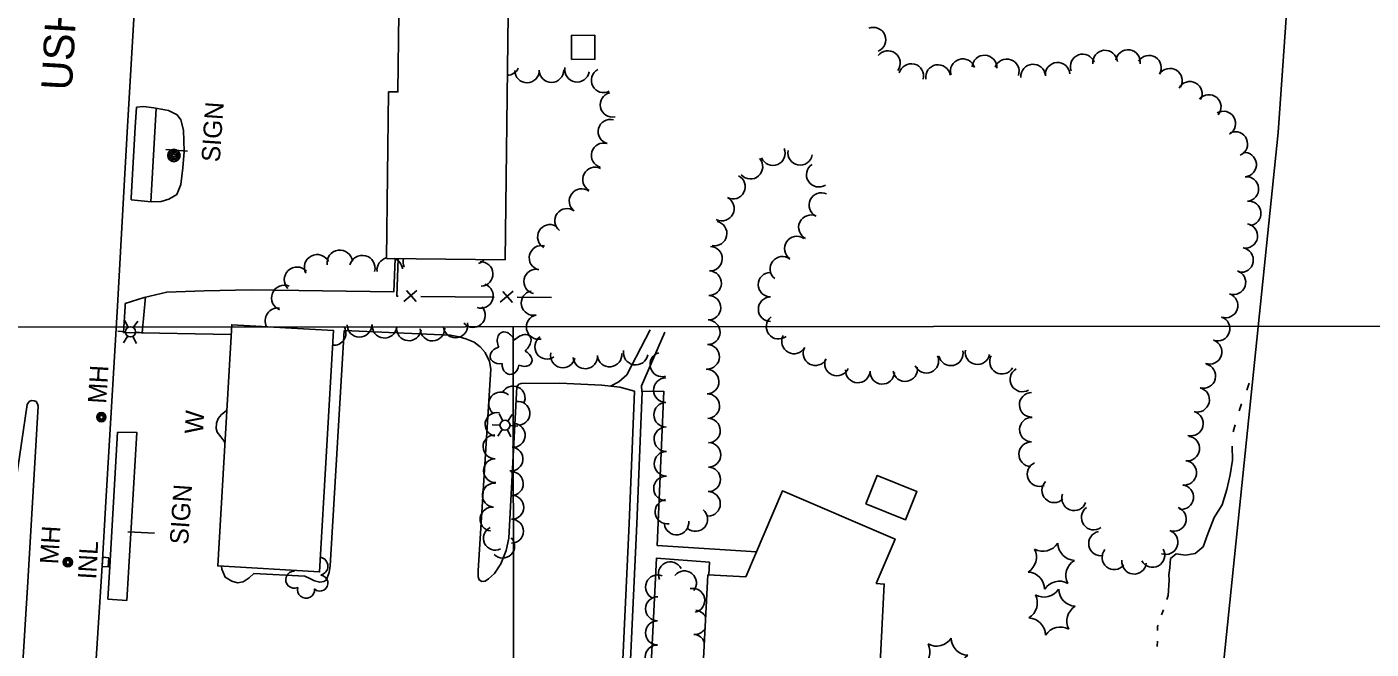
# Model space of a CAD drawing. Extents: x 189384 to 193282, y 256970 to 260388.
# Drawn here: x 190987.6 to 191426.3, y 259406.6 to 259609.6 of the extents above; entities that cross this region are included whole.
import ezdxf

# ---------------------------------------------------------------- set-up
doc = ezdxf.new("R2010")
doc.units = 0
for name, color, linetype in [('E_DRN_Grate', 7, 'Continuous'), ('E_DWY', 7, 'Continuous'), ('E_LAND_Vegetation', 7, 'Continuous'), ('E_MAP_GridLines', 7, 'Continuous'), ('E_MAP_Limits', 7, 'Continuous'), ('E_MISCPROP', 7, 'Continuous'), ('E_MISCPROP_HvyLine', 7, 'Continuous'), ('E_MISCPROP_Railing', 7, 'Continuous'), ('E_PATH_Sidewalk', 7, 'Continuous'), ('E_RDWY', 7, 'Continuous'), ('E_RDWY_Name', 7, 'Continuous'), ('E_WTR', 7, 'Continuous')]:
    doc.layers.add(name, color=color, linetype=linetype)

# ---------------------------------------------------------------- blocks, each defined once
blk = doc.blocks.new('WAL')
at = {"layer": 'E_MISCPROP_Railing'}
blk.add_text('W', height=6, rotation=360, dxfattribs=at).set_placement((-2.3, -3.01))
blk = doc.blocks.new('INLT')
at = {"layer": 'E_MISCPROP_Railing'}
blk.add_lwpolyline([(3, -2), (3, 0), (0, 0), (0, -2), (3, -2)], dxfattribs=at)
blk = doc.blocks.new('INL')
at = {"layer": 'E_MISCPROP_Railing'}
blk.add_text('INL', height=6, rotation=0, dxfattribs=at).set_placement((-5.79, -2.75))
blk = doc.blocks.new('MHO_8')
at = {"layer": 'E_DRN_Grate'}
for centre, radius in [((0.04, -0.06), 1.5), ((0.04, -0.06), 1.22), ((0.04, -0.07), 0.968), ((0.01, -0.08), 0.605)]:
    blk.add_circle(centre, radius, dxfattribs=at)
blk = doc.blocks.new('MHT_6')
at = {"layer": 'E_DRN_Grate'}
blk.add_text('MH', height=6, rotation=0.0001, dxfattribs=at).set_placement((-5.61, -3.06))
blk = doc.blocks.new('MHO_9')
at = {"layer": 'E_DRN_Grate'}
for centre, radius in [((0.04, -0.06), 1.5), ((0.04, -0.06), 1.22), ((0.04, -0.07), 0.968), ((0.01, -0.08), 0.605)]:
    blk.add_circle(centre, radius, dxfattribs=at)
blk = doc.blocks.new('MHT_7')
at = {"layer": 'E_DRN_Grate'}
blk.add_text('MH', height=6, rotation=360, dxfattribs=at).set_placement((-5.61, -3.06))
blk = doc.blocks.new('LTP')
at = {"layer": 'E_MISCPROP'}
for p, q in [((-1.61, 0.09), (-4.22, 0.17)), ((-0.78, 1.46), (-1.98, 3.76)), ((0.86, 1.37), (2.22, 3.6)), ((1.66, 0), (4.18, -0.06)), ((-0.86, -1.4), (-2.22, -3.59)), ((0.78, -1.44), (2.02, -3.62))]:
    blk.add_line(p, q, dxfattribs=at)
blk.add_circle((0.02, 0.01), 1.64, dxfattribs=at)
blk = doc.blocks.new('POLE')
at = {"layer": 'E_MISCPROP'}
for radius in [2.02, 1.51, 1.01, 0.504]:
    blk.add_circle((0.03, -0.09), radius, dxfattribs=at)
blk = doc.blocks.new('PINEL')
at = {"layer": 'E_LAND_Vegetation'}
for centre, start, end in [((-8.23, 7.26), 275.2112, 0.9761), ((2.17, 10.66), 215.2112, 300.9761), ((10.31, 3.35), 155.2112, 240.9761), ((-10.49, -3.45), 335.2112, 60.9761), ((8.05, -7.36), 95.2112, 180.9761), ((-2.35, -10.75), 35.2112, 120.9761)]:
    blk.add_arc(centre, 5.72, start, end, dxfattribs=at)
blk = doc.blocks.new('TREE')
at = {"layer": 'E_LAND_Vegetation'}
for centre, major_axis, ratio in [((-1.07, 3.38), (0.91, -3.32), 0.782863), ((2.88, 1.66), (-3.52, -1.95), 0.691916), ((-3.74, -0.07), (3.29, -0.08), 0.832022), ((-1.48, -3.66), (1.2, 3.24), 0.716896), ((2.54, -2.64), (-3.34, 3.06), 0.560249)]:
    blk.add_ellipse(centre, major_axis=major_axis, ratio=ratio, start_param=1.570796, end_param=4.712389, dxfattribs=at)
blk = doc.blocks.new('SIGN')
at = {"layer": 'E_MISCPROP'}
blk.add_text('SIGN', height=6, rotation=0, dxfattribs=at).set_placement((0, -3))

msp = doc.modelspace()

# ---------------------------------------------------------------- linework, layer by layer
at = {"layer": 'E_DWY'}
for points in [[(191023.32, 259583.42), (191025.63, 259583.6), (191029.02, 259583.16), (191033.76, 259582.25), (191036.64, 259580.89), (191037.87, 259579.25), (191038.66, 259575.89), (191038.96, 259568.92), (191038.54, 259563.57), (191037.83, 259558.12), (191036.5, 259554.95), (191033.94, 259553.35), (191031.45, 259552.63), (191028.11, 259552.5), (191021.63, 259553.12)], [(191019.72, 259519.32), (191025.86, 259521.35), (191033.22, 259523.07), (191045.41, 259523.52), (191060.76, 259523.79), (191107.35, 259523.14), (191107.74, 259534.05)], [(191019.16, 259509.86), (191054.29, 259509.24)], [(191091.17, 259510.56), (191086.57, 259433.75), (191086.2, 259431.6), (191085.63, 259429.9), (191085.22, 259429.16), (191084.48, 259428.7), (191083.16, 259428.43), (191081.47, 259428.92), (191079.99, 259429.66), (191078.36, 259430.39), (191061.68, 259431.34), (191060.15, 259429.87), (191058.21, 259428.61), (191056.28, 259428.21), (191054.5, 259428.77), (191052.35, 259430.08), (191051.26, 259432.74), (191051.08, 259433.68)], [(191185.9, 259490.73), (191181.14, 259492.08), (191175.19, 259492.67), (191161.53, 259493.33), (191148.87, 259493.21), (191148.18, 259493.07), (191147.47, 259492.14), (191144.94, 259442.85), (191144.03, 259438.76), (191142.27, 259434.44), (191140.26, 259431.29), (191138.2, 259429.54), (191137.16, 259428.82), (191136.08, 259428.65), (191135.24, 259429.21), (191134.84, 259430.2), (191134.91, 259432.25), (191139.04, 259497.88), (191138.59, 259500.44), (191137.16, 259503.38), (191135.51, 259505.21), (191133.58, 259506.7), (191130.89, 259507.81), (191128.71, 259508.49), (191125.75, 259509.03), (191122.99, 259509.11), (191091.17, 259510.56)], [(191169.01, 259347.09), (191166.8, 259347.84), (191164.86, 259349.29), (191163.51, 259351.61), (191162.86, 259353.49), (191162.74, 259355), (191162.95, 259360.41), (191163.78, 259362.92), (191165.02, 259364.61), (191166.44, 259365.79), (191168.22, 259366.62), (191169.77, 259366.82), (191180.31, 259366.31), (191182.18, 259405.49), (191184.13, 259447.55), (191185.9, 259490.73)], [(191169.82, 259349.45), (191167.98, 259350.08), (191166.76, 259350.99), (191165.79, 259352.65), (191165.33, 259354.01), (191165.24, 259355.05), (191165.44, 259359.96), (191166.03, 259361.76), (191166.85, 259362.88), (191167.79, 259363.66), (191168.93, 259364.19), (191169.88, 259364.31), (191182.69, 259363.69), (191184.68, 259405.37), (191186.63, 259447.44), (191188.4, 259490.63)], [(191017.21, 259477.39), (191023.53, 259477.27), (191020.18, 259422.51), (191013.98, 259422.91)]]:
    msp.add_lwpolyline(points, dxfattribs=at)
at = {"layer": 'E_LAND_Vegetation'}
for centre, radius, start, end in [((191263.91, 259605.38), 4.02, 292.4481, 112.4328), ((191268.61, 259597.79), 4.02, 323.4581, 143.4428), ((191293.04, 259595.13), 4.02, 17.3575, 197.3422), ((191300.13, 259596.3), 4.02, 356.9807, 176.9654), ((191307.4, 259595.08), 4.02, 340.689, 160.6737), ((191332.17, 259596.65), 4.02, 20.2273, 200.212), ((191339.51, 259597.92), 4.02, 5.5426, 185.5272), ((191346.97, 259598.08), 4.02, 351.2617, 171.2464), ((191353.81, 259596.24), 4.02, 328.2882, 148.2729), ((191144.38, 259597.81), 4, 270.2674, 334.1167), ((191150.81, 259595.35), 4, 180.86, 0.8447), ((191158.8, 259595.47), 4, 180.86, 0.8447), ((191167.16, 259595.59), 4, 170.0877, 350.0724), ((191175.8, 259592.14), 4, 118.0291, 298.0137), ((191276.22, 259593.54), 4.02, 345.262, 165.2467), ((191284.97, 259593.19), 4.02, 9.6768, 189.6615), ((191315.98, 259593.36), 4.02, 4.1451, 184.1298), ((191324, 259593.94), 4.02, 4.1451, 184.1298), ((191360.65, 259592.01), 4.02, 328.2882, 148.2729), ((191367.16, 259587.73), 4, 331.7355, 151.7202), ((191178.7, 259584.17), 4, 102.6512, 282.6359), ((191373.34, 259583.45), 4, 319.8336, 139.8183), ((191378.1, 259578.05), 4, 300.7593, 120.744), ((191178.03, 259575.42), 4, 75.4466, 255.4312), ((191382, 259571.38), 4, 293.574, 113.5587), ((191175.82, 259567.67), 4, 73.4318, 253.4165), ((191231.08, 259568.39), 4, 202.9186, 22.9033), ((191239.98, 259568.51), 4, 169.5769, 349.5616), ((191384.88, 259564.66), 4, 275.2846, 95.2692), ((191172.98, 259559.81), 4, 62.8287, 242.8133), ((191223.74, 259563.96), 4, 221.7049, 41.6896), ((191246.03, 259561.36), 4, 122.7822, 302.7669), ((191218.05, 259557.45), 4, 243.0223, 63.007), ((191385.61, 259556.7), 4, 275.2846, 95.2692), ((191168.61, 259552.75), 4, 53.4672, 233.4519), ((191246.88, 259551.45), 4, 64.762, 244.7467), ((191163.85, 259546.32), 4, 53.4672, 233.4519), ((191214.42, 259550.33), 4, 243.0223, 63.007), ((191386.35, 259548.74), 4, 275.2846, 95.2692), ((191212.06, 259542.17), 4, 258.3062, 78.2908), ((191243.47, 259544.22), 4, 64.762, 244.7467), ((191158.28, 259541.09), 4, 60.7512, 240.7358), ((191385.24, 259541.4), 4, 260.1662, 80.1509), ((191155.55, 259534.24), 4, 75.9464, 255.9311), ((191210.54, 259533.96), 4, 268.1919, 88.1765), ((191238.88, 259537.27), 4, 55.5005, 235.4852), ((191383.87, 259533.52), 4, 260.1662, 80.1509), ((191082.32, 259531.13), 4.18, 27.6143, 207.5989), ((191089.74, 259532.57), 4.18, 8.2016, 188.1863), ((191097.05, 259530.87), 4.18, 345.6516, 165.6363), ((191106.02, 259530.19), 4.18, 103.8988, 185.9866), ((191106.02, 259530.19), 4.18, 6.002, 67.5093), ((191114.54, 259532.81), 4.18, 163.254, 202.5018), ((191133.81, 259536.19), 4, 286.8783, 321.7956), ((191135.69, 259528.98), 4, 272.9498, 92.9345), ((191234.14, 259530.67), 4, 51.6086, 231.5932), ((191075.78, 259527.07), 4.18, 43.3141, 223.2988), ((191153.79, 259526.5), 4, 77.5542, 257.5389), ((191210.28, 259525.97), 4, 268.1919, 88.1765), ((191230.28, 259525.49), 4, 90.2854, 270.2701), ((191381.39, 259526.26), 4, 251.2939, 71.2786), ((191071.64, 259521.16), 4.18, 68.2709, 248.2556), ((191135.79, 259521.82), 4, 251.5014, 71.4861), ((191152.96, 259519.51), 4, 101.9589, 281.9435), ((191210.03, 259517.98), 4, 268.1919, 88.1765), ((191230.32, 259517.49), 4, 90.2854, 270.2701), ((191378.83, 259518.7), 4, 250.9634, 70.948), ((191069.53, 259513.73), 4.18, 83.061, 208.0823), ((191133.19, 259515.56), 4, 221.9478, 41.9324), ((191154.62, 259511.68), 4, 101.9589, 281.9435), ((191087.73, 259509.7), 4, 265.6919, 28.6941), ((191096.14, 259512.37), 4, 178.9526, 358.9372), ((191104.31, 259512.08), 4, 173.795, 353.7797), ((191112.26, 259511.21), 4, 173.795, 353.7797), ((191119.96, 259511.16), 4, 181.4138, 1.3985), ((191127.48, 259512.18), 4, 191.7194, 11.704), ((191209.82, 259509.97), 4, 268.6652, 88.6498), ((191232.92, 259511.78), 4, 127.4246, 307.4092), ((191376.22, 259511.15), 4, 250.9634, 70.948), ((191157.37, 259505.21), 4, 124.3118, 304.2964), ((191237.94, 259506.96), 4, 151.4461, 331.4308), ((191373.61, 259503.59), 4, 250.9634, 70.948), ((191162.54, 259502.39), 4, 167.9461, 347.9308), ((191169.86, 259502.07), 4, 184.0688, 4.0535), ((191177.78, 259502.7), 4, 185.63, 5.6147), ((191186.3, 259503.31), 4, 169.7595, 349.7442), ((191194.97, 259499.46), 4, 105.5511, 285.5357), ((191209.63, 259501.98), 4, 268.6652, 88.6498), ((191244.96, 259503.13), 4, 151.4461, 331.4308), ((191281.16, 259500.67), 4, 203.5149, 23.4995), ((191289.17, 259503.08), 4, 192.3753, 12.36), ((191297.82, 259503.45), 4, 169.9768, 349.9615), ((191305.83, 259500.35), 4, 150.2409, 330.2255), ((191209.46, 259493.88), 4, 271.6315, 91.6162), ((191251.99, 259499.76), 4, 156.5825, 336.5672), ((191258.79, 259497.5), 4, 176.8905, 356.8751), ((191274.24, 259497.93), 4, 188.9942, 8.9788), ((191312.49, 259494.57), 4, 120.544, 300.5287), ((191371.56, 259495.69), 4, 255.5156, 75.5003), ((191196.14, 259491.06), 4, 90.5168, 270.5015), ((191266.77, 259497.07), 4, 176.8905, 356.8751), ((191142.24, 259486.57), 3.9, 49.8321, 229.8168), ((191146.28, 259488.51), 3.9, 333.3946, 153.3793), ((191209.68, 259485.89), 4, 271.6315, 91.6162), ((191315.52, 259486.28), 4, 90.801, 270.7857), ((191369.55, 259487.95), 4, 255.5156, 75.5003), ((191147.87, 259483.53), 3.9, 277.6248, 97.6095), ((191196.21, 259483.07), 4, 90.5168, 270.5015), ((191141.04, 259479.91), 3.9, 78.7956, 258.7803), ((191146.29, 259476.37), 3.9, 264.8726, 84.8573), ((191209.91, 259477.9), 4, 271.6315, 91.6162), ((191315.59, 259478.19), 4, 88.2227, 268.2074), ((191367.55, 259480.21), 4, 255.5156, 75.5003), ((191140.39, 259472.63), 3.9, 91.0529, 271.0376), ((191196.29, 259475.08), 4, 90.5168, 270.5015), ((191366.34, 259472.05), 4, 262.8077, 82.7924), ((191145.59, 259468.61), 3.9, 264.8726, 84.8573), ((191210.05, 259469.99), 4, 269.4536, 89.4383), ((191315.34, 259470.2), 4, 88.2227, 268.2074), ((191140.54, 259464.84), 3.9, 91.0529, 271.0376), ((191196.36, 259467.08), 4, 90.5168, 270.5015), ((191318.08, 259463.7), 4, 113.2652, 293.2499), ((191365.33, 259464.12), 4, 262.8077, 82.7924), ((191145.69, 259460.6), 3.9, 271.4341, 91.4187), ((191196.16, 259459.01), 4, 88.3324, 268.3171), ((191209.97, 259461.99), 4, 269.4536, 89.4383), ((191140.16, 259456.85), 3.9, 85.1252, 265.1099), ((191322.89, 259458.42), 4, 134.894, 314.8786), ((191364.33, 259456.19), 4, 262.8077, 82.7924), ((191145.85, 259452.88), 3.9, 269.4553, 89.44), ((191196.64, 259451.45), 4, 98.8292, 278.8139), ((191209.9, 259454), 4, 269.4536, 89.4383), ((191329.38, 259455.79), 4, 160.2449, 340.2296), ((191139.4, 259449.02), 3.9, 82.7421, 262.7268), ((191205.75, 259449.03), 4, 229.8329, 49.8176), ((191335.76, 259449.52), 4, 125.8002, 305.7849), ((191361.96, 259449.05), 4, 250.3878, 70.3724), ((191140.51, 259442.8), 3.9, 115.6442, 295.6289), ((191145.77, 259445.09), 3.9, 269.4553, 89.44), ((191199.62, 259447.9), 4, 187.166, 7.1507), ((191338.14, 259441.06), 4, 101.168, 281.1527), ((191359.28, 259441.51), 4, 250.3878, 70.3724), ((191142.89, 259440.23), 3.9, 223.9287, 43.9134), ((191082.87, 259433.67), 2.97, 282.1074, 79.3792), ((191342.49, 259436.54), 4, 140.5431, 320.5277), ((191354.98, 259437.32), 4, 208.7186, 28.7033), ((191074.83, 259429.28), 2.78, 87.4275, 295.2005), ((191077.03, 259434.19), 2.97, 219.2959, 225.6905), ((191197.62, 259431.14), 3.94, 26.9385, 206.9232), ((191202.17, 259428.19), 3.94, 320.9573, 140.942), ((191348.97, 259435.11), 4, 172.8035, 352.7882), ((191083.25, 259428.16), 2.61, 226.8127, 84.7453), ((191193.44, 259426.88), 3.94, 67.3645, 247.3492), ((191078.69, 259426.01), 2.78, 164.1045, 5.1156), ((191193.48, 259419.79), 3.94, 89.6023, 269.587), ((191204.89, 259422.51), 3.94, 282.552, 102.5367), ((191205.6, 259415.36), 3.94, 26.1432, 85.5762), ((191193.42, 259411.92), 3.94, 89.6023, 269.587), ((191205.6, 259415.36), 3.94, 265.5916, 327.951), ((191204.99, 259407.51), 3.94, 19.3985, 85.5762), ((191193.33, 259404.03), 3.94, 89.0497, 269.0344)]:
    msp.add_arc(centre, radius, start, end, dxfattribs=at)
at = {"layer": 'E_MAP_GridLines'}
for p, q in [((190146.34, 259511.09), (191646.33, 259512.15)), ((190146.34, 259511.09), (191646.33, 259512.15)), ((190146.34, 259511.09), (191646.33, 259512.15)), ((191147.05, 258511.8), (191146.33, 259511.8))]:
    msp.add_line(p, q, dxfattribs=at)
at = {"layer": 'E_MAP_Limits'}
msp.add_lwpolyline([(191355.32, 259180.1), (191395.97, 259575.08), (191425.78, 260001.74)], dxfattribs=at)
at = {"layer": 'E_MISCPROP'}
for p, q in [((191032.95, 259569.54), (191040.02, 259569.05)), ((191020.52, 259444.92), (191029.26, 259444.47))]:
    msp.add_line(p, q, dxfattribs=at)
at = {"layer": 'E_MISCPROP_HvyLine'}
for points in [[(191143.73, 259533.64), (191143.73, 259533.64), (191144.62, 259613.61), (191144.62, 259613.61), (191108.98, 259614.01), (191108.69, 259588.35), (191108.69, 259588.35), (191108.69, 259588.35), (191105.62, 259588.38), (191105.62, 259588.38), (191105.01, 259534.08), (191143.73, 259533.64)], [(191165.29, 259606.76), (191165.29, 259606.76), (191172.93, 259606.82), (191172.99, 259599.03), (191172.99, 259599.03), (191165.35, 259598.97), (191165.29, 259606.76)], [(191087.71, 259510.49), (191087.71, 259510.49), (191083.14, 259431.81), (191083.14, 259431.81), (191049.9, 259433.75), (191054.47, 259512.42), (191054.47, 259512.42), (191087.71, 259510.49)]]:
    msp.add_lwpolyline(points, close=True, dxfattribs=at)
for points in [[(191264.76, 259427.99), (191270.97, 259442.53), (191270.97, 259442.53), (191270.97, 259442.53), (191234.18, 259458.21), (191234.18, 259458.21), (191222.2, 259430.19)], [(191206.04, 259357.2), (191209.84, 259430.83), (191209.84, 259430.83), (191222.2, 259430.19)], [(191264.76, 259427.99), (191267.42, 259427.86), (191267.42, 259427.86), (191267.42, 259427.86), (191263.66, 259354.88)]]:
    msp.add_lwpolyline(points, dxfattribs=at)
at = {"layer": 'E_MISCPROP_Railing'}
for p, q in [((191114.89, 259523.61), (191110.67, 259520)), ((191114.67, 259519.97), (191111.54, 259523.56)), ((191146.27, 259523.36), (191142.05, 259519.75)), ((191146.05, 259519.72), (191142.93, 259523.31))]:
    msp.add_line(p, q, dxfattribs=at)
for points in [[(191108.76, 259521.7), (191108.34, 259521.71), (191108.78, 259534.03)], [(191127.39, 259521.56), (191116.18, 259521.65)], [(191140.15, 259521.45), (191127.39, 259521.56)], [(191158.77, 259521.31), (191147.56, 259521.4)], [(191052.86, 259484.7), (191052.65, 259484.36), (191051.15, 259483.14), (191050, 259481.79), (191049.47, 259480.31), (191049.42, 259478.53), (191049.72, 259477.38), (191050.89, 259475.84), (191051.85, 259474.61), (191052.24, 259473.97)]]:
    msp.add_lwpolyline(points, dxfattribs=at)
at = {"layer": 'E_PATH_Sidewalk'}
for points in [[(191029.84, 259583), (191028.04, 259552.5)], [(191025.24, 259509.75), (191026.35, 259521.47)], [(191178.06, 259492.38), (191180.82, 259493.79), (191183.39, 259496.12), (191191.04, 259510.74)], [(191195.76, 259510.05), (191188.14, 259492.51), (191188.3, 259490.63), (191195.43, 259490.72), (191193.26, 259440.43), (191225.68, 259438.34)], [(191210.16, 259430.81), (191210.33, 259434.96), (191193.03, 259436.26), (191189.12, 259358.37), (191197.38, 259358.05), (191197.69, 259363.03), (191206.23, 259362.73), (191205.86, 259357.67), (191206.05, 259357.43)]]:
    msp.add_lwpolyline(points, dxfattribs=at)
msp.add_lwpolyline([(191261.37, 259454.04), (191274.32, 259448.75), (191278.1, 259458.01), (191265.14, 259463.29)], close=True, dxfattribs=at)
at = {"layer": 'E_RDWY'}
for points in [[(191048.1, 259995.99), (191043.46, 259939.63), (191039.72, 259896.92), (191035.9, 259846.97), (191033.06, 259800.26), (191028.66, 259723.54), (191025.78, 259671.21), (191024.1, 259639.83), (191022.83, 259617.71), (191020.45, 259577.04), (191019.17, 259553.9), (191017.17, 259518.52), (191013.34, 259454.66), (191012.18, 259433.77), (191008.14, 259371.5), (191003, 259311.88), (190996.25, 259252.68), (190988.62, 259194.19), (190987.97, 259190.05), (190986.58, 259181.04), (190985.91, 259175.99), (190986.1, 259170.87), (190987.75, 259163.86)], [(191023.32, 259583.42), (191022.94, 259576.9), (191021.66, 259553.76), (191021.63, 259553.12)], [(191019.72, 259519.32), (191019.67, 259518.37), (191019.16, 259509.86)], [(190967.7, 259270.09), (190970.55, 259312.1), (190972.64, 259354.58), (190973.63, 259374.5), (190974.42, 259384.22), (190978.37, 259415.58), (190983.96, 259461.15), (190987.69, 259486.37), (190988.35, 259487.34), (190989.07, 259487.66), (190989.94, 259487.65), (190990.58, 259487.35), (190991.03, 259486.65), (190991.23, 259485.88), (190987.89, 259428.62), (190984.7, 259377.84), (190982.15, 259345.94), (190977.85, 259300.18), (190974.19, 259269.46)], [(191017.21, 259477.39), (191015.84, 259454.52), (191014.68, 259433.62), (191013.98, 259422.91)]]:
    msp.add_lwpolyline(points, dxfattribs=at)
at = {"layer": 'E_WTR'}
for points in [[(191385.71, 259491.1), (191386.54, 259493.34)], [(191383.29, 259484.37), (191384.05, 259486.63)], [(191381.33, 259477.49), (191381.89, 259479.81)], [(191371.47, 259440), (191372.98, 259444.18), (191375.14, 259449.52), (191377.67, 259453.65), (191379.24, 259458.66), (191380.35, 259463.42), (191381.04, 259468.29), (191380.92, 259472.78)], [(191359.67, 259422.8), (191360.04, 259424.06), (191360.44, 259429.11), (191360.29, 259430.88), (191360.64, 259433.18), (191360.8, 259436.14), (191362.66, 259437.74), (191365.72, 259437.32), (191368.84, 259437.79), (191371.47, 259440)], [(191357.86, 259417.83), (191358.52, 259419.46)], [(191356.61, 259412.73), (191356.63, 259414.01), (191356.77, 259414.47)], [(191356.5, 259407.44), (191356.56, 259409.2)]]:
    msp.add_lwpolyline(points, dxfattribs=at)

# ---------------------------------------------------------------- block references
at = {"layer": 'E_DRN_Grate'}
for name, p, xscale, yscale, rotation in [('MHT_6', (191010.76, 259492.35), 0.9999987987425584, 0.9999987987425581, 86.69627829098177), ('MHO_8', (191011.83, 259482.24), 0.9999987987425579, 0.9999987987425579, 86.69627827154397), ('MHT_7', (190995.08, 259439.98), 0.9999979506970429, 0.9999979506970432, 86.72006162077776), ('MHO_9', (191000.9, 259434.93), 0.999997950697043, 0.9999979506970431, 86.7200615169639)]:
    msp.add_blockref(name, p, dxfattribs=dict(at, xscale=xscale, yscale=yscale, rotation=rotation))
at = {"layer": 'E_LAND_Vegetation'}
for name, p, rotation in [('TREE', (191145.61, 259503.25), 86.03297154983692), ('PINEL', (191321.86, 259433.76), 86.03296840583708), ('PINEL', (191322.16, 259418.81), 86.03296839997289), ('PINEL', (191287.1, 259402.8), 86.03296902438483)]:
    msp.add_blockref(name, p, dxfattribs=dict(at, rotation=rotation))
at = {"layer": 'E_MISCPROP'}
for name, p, xscale, yscale, rotation in [('SIGN', (191047.54, 259565.53), 1.0000023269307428, 1.000002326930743, 86.10866718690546), ('POLE', (191035.6, 259567.53), 0.9999978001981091, 0.9999978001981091, 178.52107587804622), ('LTP', (191021.44, 259510.11), 0.9999978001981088, 0.9999978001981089, 178.5210761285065), ('LTP', (191143.66, 259479.65), 0.9999978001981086, 0.9999978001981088, 178.5210739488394), ('SIGN', (191037.19, 259440.79), 1.0000023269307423, 1.0000023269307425, 86.10866736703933)]:
    msp.add_blockref(name, p, dxfattribs=dict(at, xscale=xscale, yscale=yscale, rotation=rotation))
at = {"layer": 'E_MISCPROP_Railing'}
for name, p, xscale, yscale, rotation in [('WAL', (191042.16, 259479.17), 0.9999980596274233, 0.999998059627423, 86.7061638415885), ('INL', (191007.76, 259435.22), 1.0000019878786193, 1.0000019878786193, 86.78581685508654), ('INLT', (191012.17, 259433.57), 1.0000019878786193, 1.0000019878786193, 86.78581677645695)]:
    msp.add_blockref(name, p, dxfattribs=dict(at, xscale=xscale, yscale=yscale, rotation=rotation))

# ---------------------------------------------------------------- texts
at = {"layer": 'E_RDWY_Name'}
msp.add_text('USH 51/STH 70', height=10, rotation=86.6519, dxfattribs=at).set_placement((191002.23, 259588.67))

doc.saveas('drawing.dxf')
